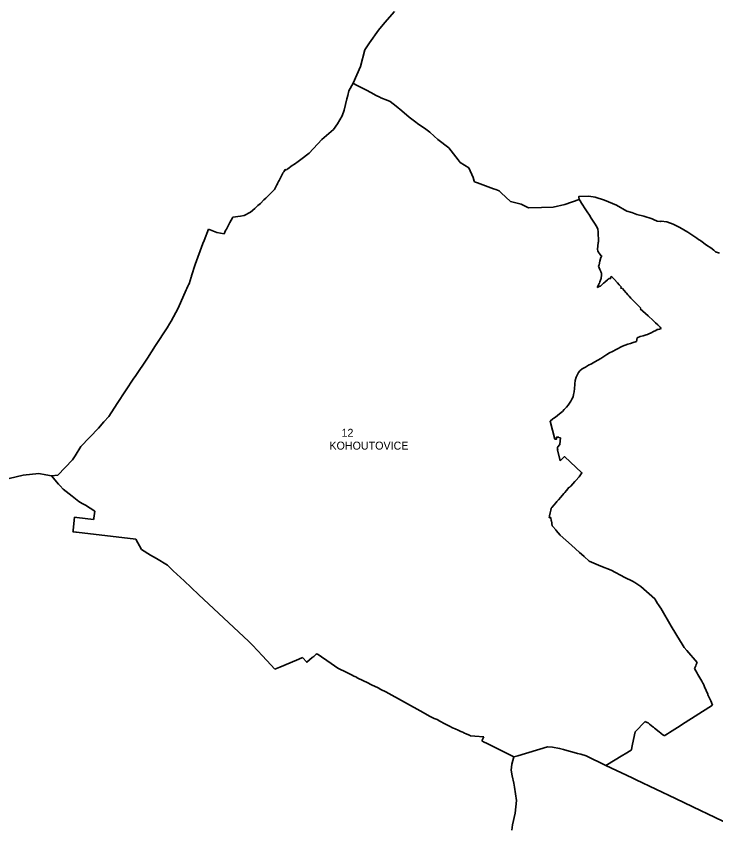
# Model space of a CAD drawing. Extents: x -610940 to -588976, y -1170376 to -1149800.
# Drawn here: x -604393 to -602206, y -1161621 to -1159085 of the extents above; entities that cross this region are included whole.
import ezdxf

# ---------------------------------------------------------------- set-up
doc = ezdxf.new("R2010")
doc.units = 0
doc.header["$LTSCALE"] = 10
doc.layers.add('54', color=7, linetype='Continuous', lineweight=35)
doc.layers.add('55', color=7, linetype='Continuous')
doc.layers.add('56', color=7, linetype='Continuous')

msp = doc.modelspace()

# ---------------------------------------------------------------- linework, layer by layer
at = {"layer": '54'}
for p, q in [((-603339.61, -1159294.37), (-603352.48, -1159318.11)), ((-603338.24, -1159295.09), (-603339.61, -1159294.37)), ((-603338.24, -1159295.09), (-603328.54, -1159300.16)), ((-603328.54, -1159300.16), (-603319.05, -1159304.88)), ((-603319.05, -1159304.88), (-603297.64, -1159315.7)), ((-603205.45, -1159365.89), (-603187.68, -1159380.54)), ((-603368.05, -1159378.29), (-603374.09, -1159396.11)), ((-603187.68, -1159380.54), (-603164.48, -1159399.67)), ((-603374.09, -1159396.11), (-603388.8, -1159421.34)), ((-603401.27, -1159438.35), (-603437.78, -1159470.04)), ((-603388.8, -1159421.34), (-603401.27, -1159438.35)), ((-603437.78, -1159470.04), (-603476.48, -1159513.14)), ((-603099.29, -1159446.71), (-603086.17, -1159459.12)), ((-603086.17, -1159459.12), (-603074.67, -1159469.98)), ((-603074.67, -1159469.98), (-603040.4, -1159496)), ((-603040.4, -1159496), (-603011.1, -1159533.64)), ((-603502.91, -1159532.17), (-603476.48, -1159513.14)), ((-603502.91, -1159532.17), (-603511.86, -1159538.63)), ((-603011.1, -1159533.64), (-603004.91, -1159541.79)), ((-603004.91, -1159541.79), (-602977.37, -1159558.56)), ((-603557.91, -1159572.68), (-603558.8, -1159573.86)), ((-603555.8, -1159570.85), (-603557.91, -1159572.68)), ((-603546.33, -1159563.61), (-603548.76, -1159565.46)), ((-602977.37, -1159558.56), (-602963.96, -1159589.09)), ((-603559.49, -1159575.26), (-603558.8, -1159573.86)), ((-603591.63, -1159632.27), (-603608.15, -1159649.1)), ((-602876.61, -1159636.81), (-602847.59, -1159663.75)), ((-603618.23, -1159658.54), (-603628.86, -1159669.5)), ((-603612.35, -1159653.24), (-603618.23, -1159658.54)), ((-602677.58, -1159672.52), (-602633.3, -1159656.98)), ((-602627.4, -1159665.38), (-602610.04, -1159692.51)), ((-603680.6, -1159707.83), (-603660.43, -1159696.85)), ((-603647.12, -1159685.42), (-603660.43, -1159696.85)), ((-602791.21, -1159683.88), (-602750.86, -1159682.42)), ((-603724.58, -1159728.88), (-603717.01, -1159714.6)), ((-603716.05, -1159712.66), (-603717.01, -1159714.6)), ((-603716.05, -1159712.66), (-603691.74, -1159709.35)), ((-603691.74, -1159709.35), (-603680.6, -1159707.83)), ((-603792.1, -1159750.27), (-603805.59, -1159785.14)), ((-603792.1, -1159750.27), (-603765.7, -1159760)), ((-603743.02, -1159764.7), (-603765.7, -1159760)), ((-602573.88, -1159821.25), (-602566.84, -1159829.36)), ((-602564.98, -1159839.07), (-602567.96, -1159850.07)), ((-602565.46, -1159882.49), (-602568.08, -1159876.2)), ((-602570.35, -1159919.67), (-602576.45, -1159932.17)), ((-602523.97, -1159906.42), (-602513.31, -1159917.84)), ((-602570.61, -1159929.31), (-602576.45, -1159932.17)), ((-602570.61, -1159929.31), (-602569.21, -1159928.7)), ((-602497.86, -1159935.28), (-602486.93, -1159947.99)), ((-602379.4, -1160056.23), (-602376.67, -1160060.68)), ((-602451.81, -1160089.83), (-602454.11, -1160100.98)), ((-602451.81, -1160089.83), (-602442.83, -1160085.17)), ((-603956.95, -1160113.22), (-603982.03, -1160153.2)), ((-602497.96, -1160116.02), (-602517.8, -1160126.18)), ((-602556.27, -1160147.74), (-602546.99, -1160141.78)), ((-604076.82, -1160294.48), (-604102.92, -1160335.18)), ((-602666.94, -1160300.28), (-602673.01, -1160306.62)), ((-604135.83, -1160371.8), (-604190.95, -1160428.72)), ((-602691.02, -1160401.66), (-602693.46, -1160421.5)), ((-602700.94, -1160440.02), (-602699.68, -1160439.32)), ((-602700.94, -1160440.02), (-602692.27, -1160473.64)), ((-602692.27, -1160473.64), (-602690.34, -1160471.76)), ((-604300.21, -1160517.34), (-604282.36, -1160520.65)), ((-604262.19, -1160518.47), (-604282.36, -1160520.65)), ((-604282.36, -1160520.65), (-604260.49, -1160546.76)), ((-602633.19, -1160523.97), (-602642.93, -1160534.97)), ((-604260.49, -1160546.76), (-604255.39, -1160551.88)), ((-604255.39, -1160551.88), (-604255.13, -1160552.15)), ((-604218.21, -1160584.35), (-604197.04, -1160601.41)), ((-604176.24, -1160612.74), (-604147.36, -1160631.15)), ((-604150.48, -1160655.75), (-604150.64, -1160656.97)), ((-604150.2, -1160653.56), (-604150.48, -1160655.75)), ((-602726.93, -1160652.02), (-602721.98, -1160651.58)), ((-602719.43, -1160661.4), (-602717.88, -1160677.31)), ((-604215.52, -1160696.07), (-604215.1, -1160692.48)), ((-604215.52, -1160696.07), (-604206.57, -1160697.1)), ((-604206.57, -1160697.1), (-604204.57, -1160697.33)), ((-604204.57, -1160697.33), (-604018.64, -1160718.63)), ((-604018.64, -1160718.63), (-604001.49, -1160750.9)), ((-604001.49, -1160750.9), (-603972.42, -1160768.58)), ((-603972.42, -1160768.58), (-603954.59, -1160779.43)), ((-603954.59, -1160779.43), (-603920.16, -1160800.37)), ((-602617.72, -1160773.2), (-602626.19, -1160765.35)), ((-603920.16, -1160800.37), (-603901.81, -1160817.56)), ((-602532.99, -1160816.04), (-602565.19, -1160802.66)), ((-602532.99, -1160816.04), (-602490.25, -1160838.97)), ((-602465.92, -1160850.12), (-602490.25, -1160838.97)), ((-602465.92, -1160850.12), (-602459.16, -1160854.22)), ((-603845.91, -1160869.96), (-603821.71, -1160892.64)), ((-603821.71, -1160892.64), (-603666.74, -1161037.88)), ((-602396.57, -1160905.32), (-602388.11, -1160919.34)), ((-602345.79, -1160990.21), (-602378.15, -1160934.55)), ((-602316.07, -1161038.07), (-602345.79, -1160990.21)), ((-603666.74, -1161037.88), (-603653.64, -1161050.16)), ((-603653.64, -1161050.16), (-603622.57, -1161083.64)), ((-602296.41, -1161066.18), (-602304.39, -1161056.89)), ((-602263.72, -1161104.25), (-602296.41, -1161066.18)), ((-603622.57, -1161083.64), (-603596.29, -1161111.96)), ((-603464.66, -1161086.79), (-603466.88, -1161088.62)), ((-603596.29, -1161111.96), (-603584.1, -1161125.1)), ((-603584.1, -1161125.1), (-603568.31, -1161118.46)), ((-602272.78, -1161123.02), (-602268.69, -1161114.61)), ((-603387.84, -1161121.78), (-603359.43, -1161135.72)), ((-603342.35, -1161144.01), (-603359.43, -1161135.72)), ((-603261.25, -1161183.64), (-603252.45, -1161188.07)), ((-603237.16, -1161196.26), (-603252.45, -1161188.07)), ((-602216.06, -1161237.45), (-602313.15, -1161299.28)), ((-602216.06, -1161237.45), (-602221.87, -1161223.74)), ((-602457.95, -1161320.68), (-602427.06, -1161288.77)), ((-603028.52, -1161308.04), (-603026.28, -1161309.07)), ((-603026.28, -1161309.07), (-603020.5, -1161311.73)), ((-602996.61, -1161322.28), (-602993.65, -1161323.71)), ((-602972.71, -1161332.82), (-602958.73, -1161334.39)), ((-602958.73, -1161334.39), (-602931.47, -1161336.06)), ((-602931.47, -1161336.06), (-602937.26, -1161349.44)), ((-602370.97, -1161330.29), (-602376.9, -1161325.53)), ((-602367.41, -1161333.16), (-602357.4, -1161327.19)), ((-602836.86, -1161399.07), (-602828.45, -1161396.62)), ((-602824.36, -1161395.45), (-602828.45, -1161396.62)), ((-602489.39, -1161389.43), (-602496.92, -1161393.96)), ((-602489.39, -1161389.43), (-602470.26, -1161377.91)), ((-602841.54, -1161611.08), (-602843.56, -1161628.3))]:
    msp.add_line(p, q, dxfattribs=at)
for points in [[(-603339.61, -1159294.37), (-603316.75, -1159241.89), (-603303.43, -1159190.25), (-603288.8, -1159168.14), (-603260.6, -1159127.91), (-603240.3, -1159104.18), (-603210.47, -1159069.53)], [(-603352.48, -1159318.11), (-603356.18, -1159331.94), (-603359.12, -1159342.52), (-603368.05, -1159378.29)], [(-603297.64, -1159315.7), (-603284.31, -1159322.96), (-603267.26, -1159332.24), (-603256.42, -1159337.97), (-603252.46, -1159339.61), (-603231.39, -1159348), (-603223.32, -1159351.17), (-603205.45, -1159365.89)], [(-603164.48, -1159399.67), (-603147.42, -1159412.8), (-603134.5, -1159422.75), (-603116.76, -1159434.82), (-603099.29, -1159446.71)], [(-603511.86, -1159538.63), (-603522.93, -1159546.48), (-603529.81, -1159551.42), (-603543.68, -1159561.58), (-603546.33, -1159563.61)], [(-603548.76, -1159565.46), (-603551.56, -1159563.76), (-603555.8, -1159570.85)], [(-603559.49, -1159575.26), (-603560.47, -1159577.48), (-603570.76, -1159597.95), (-603572.35, -1159601.16), (-603575.71, -1159607.92), (-603576.04, -1159608.58), (-603576.16, -1159608.83), (-603577.79, -1159611.87), (-603585.27, -1159626.39), (-603588.88, -1159629.58), (-603591.63, -1159632.27)], [(-602963.96, -1159589.09), (-602960.71, -1159600.04), (-602959.98, -1159602.48)], [(-602876.61, -1159636.81), (-602881.93, -1159631.87), (-602883.46, -1159630.45), (-602893.97, -1159626.61), (-602900.46, -1159624.23), (-602934.62, -1159611.72), (-602950.86, -1159605.81), (-602959.98, -1159602.48)], [(-602194.77, -1159825.57), (-602206.77, -1159820.46), (-602212.4, -1159815.58), (-602221.67, -1159808.16), (-602234.47, -1159799.61), (-602252.66, -1159787.03), (-602256.15, -1159784.7), (-602260.12, -1159782.17), (-602264.95, -1159778.11), (-602293.76, -1159759.74), (-602318.27, -1159744.86), (-602339.44, -1159734.71), (-602358.84, -1159727.43), (-602376.66, -1159724.86), (-602380.28, -1159726.55), (-602389.64, -1159725.52), (-602400.34, -1159719.89), (-602405.09, -1159718.23), (-602430.57, -1159709.41), (-602452.82, -1159704.18), (-602468.19, -1159697.78), (-602483.62, -1159693.94), (-602516.61, -1159674.81), (-602553.61, -1159659.23), (-602583.43, -1159650.21), (-602602.94, -1159647), (-602634, -1159647.75), (-602633.76, -1159650.09), (-602633.3, -1159656.98)], [(-603647.12, -1159685.42), (-603637.23, -1159676.6), (-603628.86, -1159669.5)], [(-603608.15, -1159649.1), (-603610.55, -1159651.35), (-603612.35, -1159653.24)], [(-602791.21, -1159683.88), (-602814.27, -1159671.78), (-602847.59, -1159663.75)], [(-602677.58, -1159672.52), (-602714.75, -1159681.52), (-602750.86, -1159682.42)], [(-602627.4, -1159665.38), (-602629.23, -1159662.8), (-602633.3, -1159656.98)], [(-602573.88, -1159821.25), (-602575.16, -1159817.3), (-602575.31, -1159813.32), (-602573.13, -1159791.99), (-602572.87, -1159789.4), (-602573.94, -1159758.25), (-602574.9, -1159750.25), (-602577.72, -1159742.33), (-602584.65, -1159731.7), (-602597.06, -1159712.66), (-602599.12, -1159709.27), (-602610.04, -1159692.51)], [(-603724.58, -1159728.88), (-603731.12, -1159741.44), (-603735.86, -1159750.3), (-603738.02, -1159754.65), (-603743.02, -1159764.7)], [(-603805.59, -1159785.14), (-603809.42, -1159795.04), (-603833.68, -1159860.47)], [(-602568.08, -1159876.2), (-602572.3, -1159866.09), (-602570.99, -1159861.25), (-602567.96, -1159850.07)], [(-602564.98, -1159839.07), (-602564.01, -1159837.13), (-602563.32, -1159835.74), (-602562.6, -1159834.3), (-602565.04, -1159832.55), (-602566.84, -1159829.36)], [(-603845.24, -1159897.77), (-603844.81, -1159896.37), (-603833.68, -1159860.47)], [(-603845.24, -1159897.77), (-603846.01, -1159900.49), (-603852.28, -1159920.46), (-603853.67, -1159923.62), (-603855.77, -1159928.37), (-603859.04, -1159935.74), (-603860.93, -1159940.01), (-603886.22, -1159997.03), (-603908.62, -1160038.09), (-603913.09, -1160045.46), (-603921, -1160058.37), (-603956.95, -1160113.22)], [(-602570.35, -1159919.67), (-602569.69, -1159918.32), (-602568.46, -1159915.17), (-602565.08, -1159906.59), (-602564.28, -1159904.56), (-602564.25, -1159903.98), (-602563.64, -1159893.19), (-602563.44, -1159889.61), (-602563.37, -1159888.44), (-602563.32, -1159887.63), (-602564.02, -1159885.95), (-602564.92, -1159883.8), (-602565.46, -1159882.49)], [(-602539.24, -1159903.89), (-602534.77, -1159904.39), (-602534.25, -1159899.53)], [(-602523.97, -1159906.42), (-602526.48, -1159903.73), (-602530.55, -1159899.38), (-602532.96, -1159898.4), (-602534.25, -1159899.53)], [(-602539.24, -1159903.89), (-602542.16, -1159906.44), (-602544.95, -1159908.87), (-602552.4, -1159915.39), (-602555.03, -1159917.68), (-602556.83, -1159919.26), (-602560.79, -1159922.72), (-602564.58, -1159926.03), (-602565.55, -1159926.88), (-602566.5, -1159927.71), (-602567.42, -1159928.04), (-602567.75, -1159928.16), (-602569.21, -1159928.7)], [(-602502.15, -1159930.29), (-602507.65, -1159923.89), (-602513.31, -1159917.84)], [(-602502.15, -1159930.29), (-602502.65, -1159934.77), (-602497.86, -1159935.28)], [(-602454.99, -1159982.23), (-602457.72, -1159979.5), (-602458.43, -1159978.79), (-602471.26, -1159966.22), (-602476.69, -1159959.91), (-602480.44, -1159955.55), (-602485.24, -1159949.96), (-602486.93, -1159947.99)], [(-602448.66, -1159988.56), (-602453.88, -1159983.34), (-602454.99, -1159982.23)], [(-602442.04, -1159999.31), (-602440.3, -1159997.07), (-602444.35, -1159992.96), (-602448.66, -1159988.56)], [(-602442.04, -1159999.31), (-602417.84, -1160021.35), (-602402.17, -1160035.77)], [(-602394.68, -1160042.47), (-602398.46, -1160039.02), (-602402.17, -1160035.77)], [(-602379.4, -1160056.23), (-602386.92, -1160049.12), (-602394.68, -1160042.47)], [(-602415.31, -1160077.45), (-602418.9, -1160079.13), (-602423.98, -1160080.33), (-602433.28, -1160082.93), (-602442.83, -1160085.17)], [(-602415.31, -1160077.45), (-602408.26, -1160073.95), (-602400.79, -1160069.91)], [(-602385.66, -1160063.24), (-602388.97, -1160064.06), (-602393.54, -1160066.28), (-602400.79, -1160069.91)], [(-602385.66, -1160063.24), (-602382.38, -1160062.3), (-602376.67, -1160060.68)], [(-602454.11, -1160100.98), (-602463.77, -1160104.56), (-602472.19, -1160107.12), (-602480.64, -1160109.92), (-602489.35, -1160113.05), (-602497.96, -1160116.02)], [(-602517.8, -1160126.18), (-602528.67, -1160132.05), (-602537.72, -1160136.81), (-602546.99, -1160141.78)], [(-603982.03, -1160153.2), (-604021.32, -1160210.2), (-604025.15, -1160215.75), (-604076.82, -1160294.48)], [(-602556.27, -1160147.74), (-602565.2, -1160153.81), (-602575.05, -1160159.68), (-602584.08, -1160164.86), (-602594.61, -1160170.8), (-602603.46, -1160175.42)], [(-602623.72, -1160186.46), (-602612.98, -1160181.16), (-602603.46, -1160175.42)], [(-602623.72, -1160186.46), (-602631.24, -1160193.19), (-602634.83, -1160197.82), (-602637.17, -1160202.4), (-602642.5, -1160212.14), (-602645.49, -1160223.48), (-602645.54, -1160225.81), (-602646.28, -1160229.95), (-602646.83, -1160237.84)], [(-602648.06, -1160251), (-602648.6, -1160255.01), (-602649.05, -1160258.37), (-602650.34, -1160266.42), (-602651.52, -1160274.44), (-602655.71, -1160281.42), (-602659.42, -1160287.3), (-602663.33, -1160294.11), (-602666.94, -1160300.28)], [(-602646.83, -1160237.84), (-602647.75, -1160246.07), (-602648.06, -1160251)], [(-602673.01, -1160306.62), (-602679.37, -1160313.12), (-602685.42, -1160319.51), (-602694.93, -1160327.11), (-602707.49, -1160337.58), (-602711.91, -1160341.12), (-602714.85, -1160343.16)], [(-604102.92, -1160335.18), (-604118.41, -1160352.6), (-604135.83, -1160371.8)], [(-602714.85, -1160343.16), (-602724, -1160350.55), (-602709.41, -1160406.01)], [(-602709.41, -1160406.01), (-602704.23, -1160406.62), (-602703.51, -1160399.58), (-602696.63, -1160400.42), (-602696.69, -1160400.91), (-602691.02, -1160401.66)], [(-604190.95, -1160428.72), (-604208.8, -1160458.58), (-604216.85, -1160470.45), (-604262.19, -1160518.47)], [(-602693.46, -1160421.5), (-602693.82, -1160422.72), (-602699.64, -1160429.87), (-602701.02, -1160432.61), (-602701.24, -1160434.65), (-602700.83, -1160436.61), (-602699.68, -1160439.32)], [(-602690.34, -1160471.76), (-602679.21, -1160460.95), (-602624.31, -1160511.06), (-602633.19, -1160523.97)], [(-604436.45, -1160534.91), (-604371.16, -1160519), (-604322.33, -1160514.01), (-604300.21, -1160517.34)], [(-602642.93, -1160534.97), (-602645.4, -1160537.73), (-602646.42, -1160538.86), (-602652.94, -1160546.12), (-602659.55, -1160553.35), (-602660.61, -1160554.51), (-602663.02, -1160557.14), (-602664.03, -1160556.24), (-602665.05, -1160557.47), (-602672.4, -1160566.3), (-602677.66, -1160572.62), (-602678.56, -1160573.71), (-602680.76, -1160576.35), (-602690.64, -1160587.96), (-602697.48, -1160595.6), (-602700.47, -1160598.94), (-602702.49, -1160601.28), (-602704.75, -1160603.91), (-602705.8, -1160605.13), (-602711.42, -1160611.67), (-602718.72, -1160619.94), (-602720.36, -1160621.79)], [(-604255.13, -1160552.15), (-604245.47, -1160562.08), (-604218.21, -1160584.35)], [(-604197.04, -1160601.41), (-604186.28, -1160607.4), (-604176.24, -1160612.74)], [(-604147.36, -1160631.15), (-604148.36, -1160639.06), (-604150.2, -1160653.56)], [(-602726.93, -1160652.02), (-602725.88, -1160647.7), (-602725.79, -1160647.31), (-602725.55, -1160646.19), (-602725.48, -1160645.86), (-602723.53, -1160636.65), (-602721.73, -1160628.21), (-602721.54, -1160627.36), (-602721.48, -1160627.06), (-602721.21, -1160625.78), (-602721.02, -1160624.91), (-602720.36, -1160621.79)], [(-604215.1, -1160692.48), (-604214.84, -1160690.23), (-604210.15, -1160650.24)], [(-604150.64, -1160656.97), (-604203.31, -1160651.01), (-604210.15, -1160650.24)], [(-602719.43, -1160661.4), (-602720.25, -1160661.57), (-602721.98, -1160651.58)], [(-602717.88, -1160677.31), (-602715.01, -1160679.39), (-602705.99, -1160689.82), (-602704.51, -1160691.52)], [(-602704.51, -1160691.52), (-602692.11, -1160705.85), (-602656.63, -1160737.43)], [(-602656.63, -1160737.43), (-602631.6, -1160760.39), (-602626.19, -1160765.35)], [(-602617.72, -1160773.2), (-602601.32, -1160787.05), (-602565.19, -1160802.66)], [(-603901.81, -1160817.56), (-603867.92, -1160849.33), (-603845.91, -1160869.96)], [(-602396.57, -1160905.32), (-602439.86, -1160866.76), (-602449.19, -1160860.7), (-602459.16, -1160854.22)], [(-602378.15, -1160934.55), (-602379.22, -1160932.92), (-602385.15, -1160923.87), (-602388.11, -1160919.34)], [(-602304.39, -1161056.89), (-602310.63, -1161046.85), (-602313.99, -1161041.43), (-602316.07, -1161038.07)], [(-603568.31, -1161118.46), (-603536.32, -1161105), (-603508.77, -1161093.4), (-603498.19, -1161088.95)], [(-603498.19, -1161088.95), (-603484.32, -1161103.57), (-603467.08, -1161088.79), (-603466.88, -1161088.62)], [(-603460.1, -1161083.02), (-603462.72, -1161085.19), (-603464.66, -1161086.79)], [(-603452.3, -1161076.6), (-603454.77, -1161078.63), (-603457.7, -1161081.04), (-603460.1, -1161083.02)], [(-603387.84, -1161121.78), (-603408.19, -1161107.51), (-603452.3, -1161076.6)], [(-602268.69, -1161114.61), (-602266.79, -1161110.64), (-602263.72, -1161104.25)], [(-603261.25, -1161183.64), (-603282.3, -1161173.54), (-603296.1, -1161166.78), (-603307.04, -1161161.5), (-603327.28, -1161151.63), (-603328.14, -1161150.95), (-603331.52, -1161149.34), (-603337.61, -1161146.35), (-603342.35, -1161144.01)], [(-602222.44, -1161222.23), (-602224.51, -1161217.66), (-602230.38, -1161204.68), (-602230.9, -1161203.54), (-602240.93, -1161180.25), (-602243.54, -1161174.2), (-602244.68, -1161171.56), (-602246.45, -1161168.48), (-602249.67, -1161162.87), (-602252.64, -1161157.7), (-602255.61, -1161152.54), (-602258.67, -1161147.23), (-602261.84, -1161141.72), (-602264.51, -1161137.11), (-602268.3, -1161130.59), (-602272.78, -1161123.02)], [(-603028.52, -1161308.04), (-603036.68, -1161303.97), (-603044.85, -1161299.75), (-603053.07, -1161295.54), (-603068.53, -1161287.05), (-603077.28, -1161282.66), (-603086.33, -1161278.66), (-603100.55, -1161271.39), (-603121, -1161260), (-603237.16, -1161196.26)], [(-602221.87, -1161223.74), (-602222.05, -1161223.26), (-602222.44, -1161222.23)], [(-602427.06, -1161288.77), (-602426.48, -1161289.02), (-602424.68, -1161289.79), (-602423.64, -1161290.23)], [(-602376.9, -1161325.53), (-602377.23, -1161325.26), (-602382.6, -1161320.98), (-602397.45, -1161308.99), (-602400.6, -1161306.46), (-602402.55, -1161304.89), (-602407.87, -1161300.61), (-602412.86, -1161296.59), (-602417.3, -1161293.03), (-602423.64, -1161290.23)], [(-603020.5, -1161311.73), (-603011.6, -1161315.65), (-603002.62, -1161319.39), (-602996.61, -1161322.28)], [(-602457.95, -1161320.68), (-602466.24, -1161358.89), (-602468.49, -1161369.52), (-602468.85, -1161371.23), (-602469.87, -1161376.05), (-602470.26, -1161377.91)], [(-602357.4, -1161327.19), (-602350.32, -1161322.96), (-602317.5, -1161302.06), (-602313.15, -1161299.28)], [(-602993.65, -1161323.71), (-602983.9, -1161328.18), (-602976.1, -1161331.23), (-602972.71, -1161332.82)], [(-602367.41, -1161333.16), (-602369.38, -1161331.57), (-602370.97, -1161330.29)], [(-602937.26, -1161349.44), (-602930.07, -1161352.81), (-602922.63, -1161356.49), (-602918.21, -1161358.68), (-602893.77, -1161370.88), (-602887.12, -1161374.18), (-602836.86, -1161399.07)], [(-602824.36, -1161395.45), (-602731.77, -1161367.94), (-602716.05, -1161368.5)], [(-602610.92, -1161395.93), (-602627.77, -1161390.93), (-602638.71, -1161388.19), (-602648.57, -1161385.3), (-602660.21, -1161381.99), (-602671.24, -1161378.96), (-602682.23, -1161376.07), (-602694.17, -1161372.74), (-602716.05, -1161368.5)], [(-602610.92, -1161395.93), (-602549.5, -1161425.63), (-602496.92, -1161393.96)], [(-602836.86, -1161399.07), (-602843.33, -1161422.21), (-602845.72, -1161440.34), (-602842.08, -1161458.61)], [(-602549.5, -1161425.63), (-602467.35, -1161464.93), (-602457.38, -1161469.65), (-602455.04, -1161470.76), (-602331.71, -1161529.05), (-602277.37, -1161555.05), (-602207.92, -1161588.29), (-602157.72, -1161612.88)], [(-602842.08, -1161458.61), (-602837.53, -1161481.41), (-602835.02, -1161494)], [(-602835.02, -1161494), (-602829.35, -1161535.6), (-602832.72, -1161575.3), (-602841.54, -1161611.08)]]:
    msp.add_lwpolyline(points, dxfattribs=at)

# ---------------------------------------------------------------- texts
at = {"layer": '55'}
msp.add_text('KOHOUTOVICE ', height=25, dxfattribs=at).set_placement((-603413.65, -1160439))
at = {"layer": '56'}
msp.add_text('12 ', height=25, dxfattribs=at).set_placement((-603375.93, -1160398.96))

doc.saveas('drawing.dxf')
